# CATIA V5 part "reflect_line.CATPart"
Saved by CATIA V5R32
Part number: Part1
Bounding box of the stored display mesh (mm): x -137.722 to 27.889, y -12.795 to 48.468, z 0 to 139
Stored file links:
  D:\PROJECTS\Project 2022\CATIA V5 6R 2022\Resources\Part Files\c17_catia_v6_6r2022_prt\reflect_line.CATPart
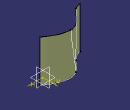
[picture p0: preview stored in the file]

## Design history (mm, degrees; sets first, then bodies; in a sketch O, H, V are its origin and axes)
Set1
  Sketch1 on xy-plane, origin (0, 0, 0), H (1, 0, 0), V (0, 1, 0)
    spline S1 through (27.8894, 17.3949) (-93.4438, 17.3949) (-113.5702, -2.4439) (-137.7218, -12.7946)
  Extrude1: Element1 Sketch1, Lim1 139, Lim2 0
  ReflectLine1: Support Extrude1, Direction (0, 0, 1), Angle 64, Origin vertex [face of Extrude1 from Sketch1.S1]
Body1 (main body)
